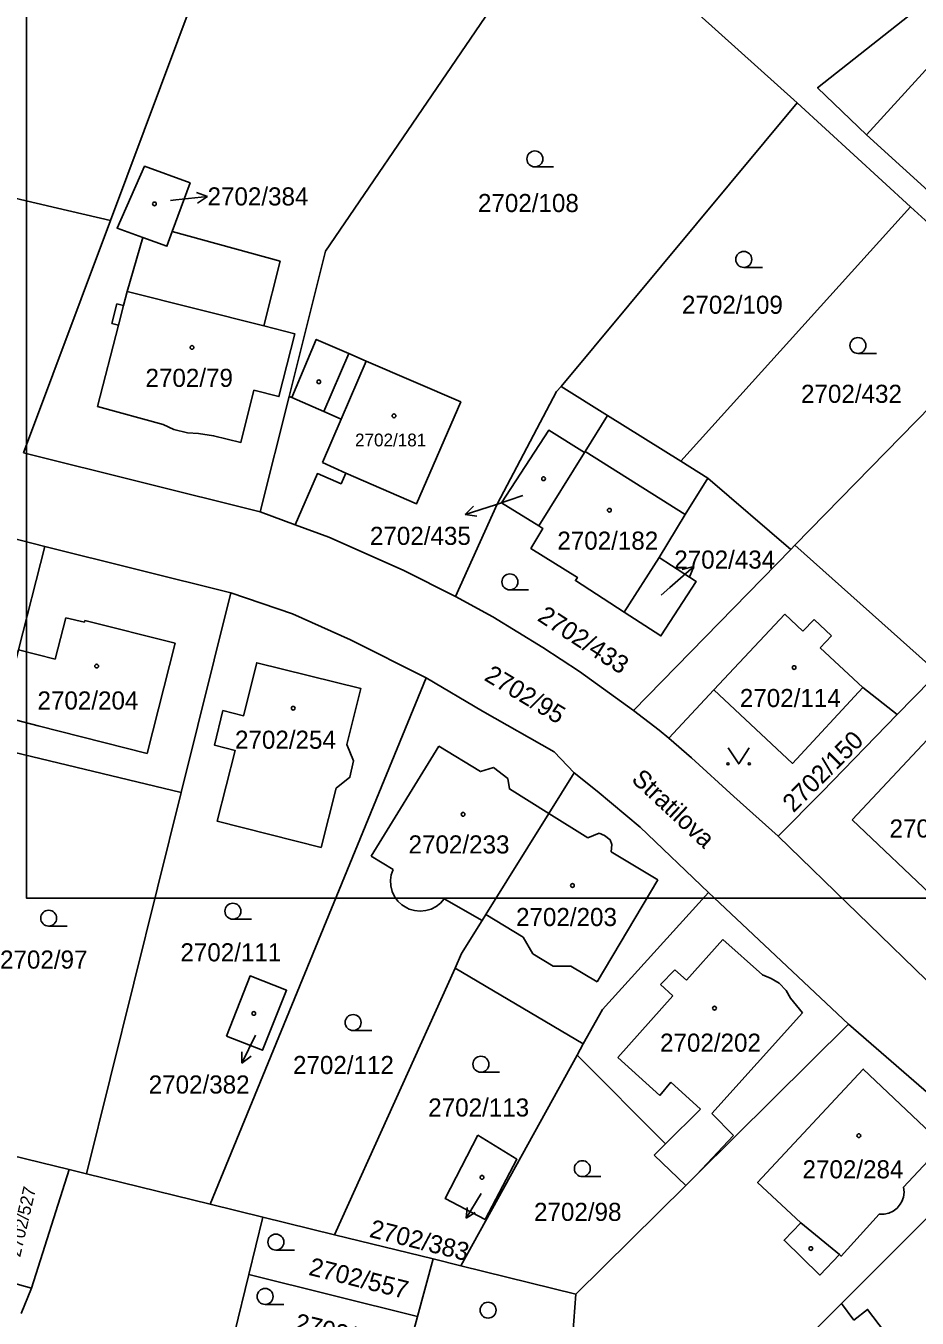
# Model space of a CAD drawing. Extents: x -496682 to -495776, y -1088797 to -1088018.
# Drawn here: x -496557.4 to -496473.7, y -1088500.7 to -1088379.3 of the extents above; entities that cross this region are included whole.
import ezdxf

# ---------------------------------------------------------------- set-up
doc = ezdxf.new("R2010")
doc.units = 0
for name, color, linetype in [('Hranice parcel', 7, 'Continuous'), ('Parcelní čísla', 7, 'Continuous'), ('Pop  PČ popisy', 7, 'Continuous'), ('Vnitřní kresba', 7, 'Continuous'), ('Vrstva 63', 7, 'Continuous'), ('Značky budov', 7, 'Continuous'), ('Značky kultur', 7, 'Continuous')]:
    doc.layers.add(name, color=color, linetype=linetype)

msp = doc.modelspace()

# ---------------------------------------------------------------- linework, layer by layer
at = {"layer": 'Hranice parcel'}
for p, q in [((-496549.47, -1088397.55), (-496534.41, -1088357.28)), ((-496484.94, -1088386.51), (-496506.52, -1088367.06)), ((-496507.11, -1088413.15), (-496484.94, -1088386.51)), ((-496474.27, -1088396.26), (-496484.94, -1088386.51)), ((-496495.87, -1088420.18), (-496474.27, -1088396.26)), ((-496557.63, -1088419.38), (-496549.47, -1088397.55)), ((-496463.6, -1088406), (-496485.14, -1088428.06)), ((-496507.11, -1088413.15), (-496502.75, -1088415.88)), ((-496535.38, -1088424.94), (-496532.68, -1088414.09)), ((-496502.75, -1088415.88), (-496495.87, -1088420.18)), ((-496557.63, -1088419.38), (-496535.38, -1088424.94)), ((-496504.92, -1088419.36), (-496509.22, -1088426.26)), ((-496493.32, -1088421.78), (-496495.87, -1088420.18)), ((-496580.96, -1088421.7), (-496555.62, -1088428.18)), ((-496493.32, -1088421.78), (-496485.53, -1088428.46)), ((-496532.1, -1088426.15), (-496535.38, -1088424.94)), ((-496555.62, -1088428.18), (-496538.16, -1088432.53)), ((-496485.53, -1088428.46), (-496500.3, -1088443.59)), ((-496485.14, -1088428.06), (-496485.53, -1088428.46)), ((-496471.71, -1088440.06), (-496485.14, -1088428.06)), ((-496501.2, -1088434.35), (-496497.9, -1088429.23)), ((-496538.16, -1088432.53), (-496542.82, -1088451.3)), ((-496540.08, -1088490.01), (-496519.8, -1088440.54)), ((-496472.38, -1088440.74), (-496475.55, -1088443.98)), ((-496542.82, -1088451.3), (-496560.5, -1088447.06)), ((-496524.96, -1088457.28), (-496518.62, -1088446.95)), ((-496513.47, -1088448.95), (-496512.11, -1088449.99)), ((-496508.27, -1088453.28), (-496505.89, -1088449.46)), ((-496551.73, -1088487.14), (-496542.82, -1088451.3)), ((-496486.71, -1088455.42), (-496471.75, -1088469.95)), ((-496522.91, -1088458.54), (-496524.96, -1088457.28)), ((-496493.26, -1088460.72), (-496480.12, -1088473.09)), ((-496514.53, -1088463.34), (-496518.09, -1088461.3)), ((-496528.42, -1088492.87), (-496517.08, -1088467.81)), ((-496505.03, -1088474.94), (-496517.08, -1088467.81)), ((-496480.12, -1088473.09), (-496466.41, -1088484.97)), ((-496505.61, -1088476), (-496505.03, -1088474.94)), ((-496516.53, -1088495.79), (-496505.61, -1088476)), ((-496562.76, -1088484.43), (-496553.34, -1088486.74)), ((-496480.76, -1088499.32), (-496466.41, -1088484.97)), ((-496495.38, -1088488.23), (-496498.38, -1088485.38)), ((-496553.34, -1088486.74), (-496556.89, -1088497.88)), ((-496551.73, -1088487.14), (-496553.34, -1088486.74)), ((-496540.08, -1088490.01), (-496551.73, -1088487.14)), ((-496495.38, -1088488.23), (-496505.72, -1088498.45)), ((-496535.15, -1088491.22), (-496540.08, -1088490.01)), ((-496536.46, -1088496.6), (-496535.15, -1088491.22)), ((-496535.15, -1088491.22), (-496528.42, -1088492.87)), ((-496528.42, -1088492.87), (-496519.15, -1088495.15)), ((-496565.8, -1088495.44), (-496556.89, -1088497.88)), ((-496520.6, -1088500.55), (-496519.15, -1088495.15)), ((-496519.15, -1088495.15), (-496516.53, -1088495.79)), ((-496505.72, -1088498.45), (-496516.53, -1088495.79)), ((-496537.8, -1088502.11), (-496536.46, -1088496.6)), ((-496520.6, -1088500.55), (-496536.46, -1088496.6)), ((-496556.89, -1088497.88), (-496557.86, -1088500.28)), ((-496505.72, -1088498.45), (-496506.52, -1088508.66)), ((-496479.61, -1088500.91), (-496480.76, -1088499.32)), ((-496522.01, -1088505.76), (-496520.6, -1088500.55))]:
    msp.add_line(p, q, dxfattribs=at)
for points in [[(-496532.68, -1088414.09), (-496529.27, -1088400.43), (-496506.52, -1088367.06)], [(-496458.81, -1088390.16), (-496459.62, -1088391.05), (-496452.7, -1088397.45), (-496448.2, -1088392.71), (-496455.1, -1088386.16), (-496452.66, -1088383.51), (-496456.87, -1088379.65), (-496455.18, -1088377.81), (-496462.05, -1088371.53), (-496462.96, -1088372.53), (-496463.92, -1088371.65), (-496464.44, -1088372.21), (-496465.37, -1088371.11), (-496483.02, -1088385.08), (-496478.41, -1088389.5), (-496471.58, -1088395.72), (-496463.03, -1088386.33), (-496458.81, -1088390.16)], [(-496574.52, -1088391.68), (-496554.43, -1088396.39), (-496549.47, -1088397.55)], [(-496546.43, -1088399.15), (-496548.84, -1088398.28), (-496546.26, -1088392.45), (-496541.98, -1088394.02), (-496543.65, -1088398.6)], [(-496474.27, -1088396.26), (-496465.34, -1088404.42), (-496463.6, -1088406)], [(-496543.65, -1088398.6), (-496533.53, -1088401.39), (-496535.05, -1088407.46), (-496532.14, -1088408.2), (-496533.63, -1088414.1), (-496535.98, -1088413.51), (-496537.21, -1088418.41), (-496539.77, -1088417.78), (-496541.18, -1088417.56), (-496542.21, -1088417.51), (-496543.51, -1088417.18), (-496544.5, -1088416.71), (-496550.68, -1088415.02), (-496548.71, -1088407.38), (-496549.32, -1088407.23), (-496548.85, -1088405.39), (-496548.24, -1088405.55), (-496547.9, -1088404.23), (-496546.43, -1088399.15)], [(-496543.65, -1088398.6), (-496544.16, -1088399.98), (-496546.43, -1088399.15)], [(-496532.68, -1088414.09), (-496532.43, -1088414.19), (-496530.13, -1088408.73), (-496527.05, -1088410.06), (-496525.42, -1088410.77), (-496516.55, -1088414.6), (-496520.69, -1088424.17), (-496527.35, -1088421.29), (-496527.79, -1088422.29), (-496530.01, -1088421.34), (-496532.1, -1088426.15)], [(-496517.03, -1088432.88), (-496513.11, -1088424.21), (-496507.54, -1088413.62), (-496507.11, -1088413.15)], [(-496502.75, -1088415.88), (-496504.86, -1088419.27), (-496504.92, -1088419.36)], [(-496509.22, -1088426.26), (-496512.71, -1088424.09), (-496508.27, -1088417.26), (-496504.92, -1088419.36)], [(-496497.9, -1088429.23), (-496495.45, -1088425.18), (-496493.32, -1088421.78)], [(-496517.03, -1088432.88), (-496521.97, -1088430.43), (-496528.95, -1088427.3), (-496532.1, -1088426.15)], [(-496509.22, -1088426.26), (-496508.83, -1088426.51), (-496509.96, -1088428.37), (-496505.58, -1088431.1), (-496505.77, -1088431.4), (-496501.2, -1088434.35)], [(-496555.62, -1088428.18), (-496558.12, -1088437.89), (-496559.72, -1088444.15), (-496560.5, -1088447.06)], [(-496497.9, -1088429.23), (-496494.43, -1088431.47), (-496497.73, -1088436.59), (-496501.2, -1088434.35)], [(-496538.16, -1088432.53), (-496532.37, -1088434.53), (-496526.9, -1088436.97), (-496519.8, -1088440.54)], [(-496500.3, -1088443.59), (-496505.39, -1088439.93), (-496508.83, -1088437.68), (-496513.52, -1088434.81), (-496517.03, -1088432.88)], [(-496529.66, -1088456.47), (-496539.44, -1088453.99), (-496537.75, -1088447.35), (-496539.7, -1088446.85), (-496538.9, -1088443.61), (-496536.95, -1088444.09), (-496535.71, -1088439.11), (-496525.94, -1088441.53), (-496527.25, -1088446.79), (-496526.61, -1088448.32), (-496526.96, -1088449.87), (-496528.25, -1088450.89), (-496529.66, -1088456.47)], [(-496519.8, -1088440.54), (-496514.5, -1088443.66), (-496507.77, -1088447.5), (-496505.89, -1088449.46)], [(-496497, -1088446.21), (-496492.75, -1088441.67), (-496485.37, -1088448.58), (-496478.75, -1088441.43), (-496475.55, -1088443.98)], [(-496497, -1088446.21), (-496497.89, -1088445.44), (-496500.3, -1088443.59)], [(-496475.55, -1088443.98), (-496482.58, -1088451.24), (-496486.71, -1088455.42)], [(-496518.62, -1088446.95), (-496514.7, -1088449.35), (-496513.47, -1088448.95)], [(-496486.71, -1088455.42), (-496490.9, -1088451.69), (-496494.87, -1088448.06), (-496497, -1088446.21)], [(-496505.89, -1088449.46), (-496503.74, -1088451.18), (-496499.69, -1088454.56), (-496493.26, -1088460.72)], [(-496512.11, -1088449.99), (-496511.97, -1088450.97), (-496508.27, -1088453.28)], [(-496508.27, -1088453.28), (-496514.18, -1088462.78), (-496514.53, -1088463.34)], [(-496518.09, -1088461.3), (-496518.44, -1088461.7), (-496518.85, -1088462.02), (-496519.33, -1088462.26), (-496519.83, -1088462.41), (-496520.36, -1088462.46), (-496520.89, -1088462.41), (-496521.39, -1088462.26), (-496521.62, -1088462.16), (-496522.07, -1088461.87), (-496522.45, -1088461.51), (-496522.76, -1088461.08), (-496522.99, -1088460.6), (-496523.12, -1088460.09), (-496523.15, -1088459.56), (-496523.08, -1088459.04), (-496522.91, -1088458.54)], [(-496505.03, -1088474.94), (-496503.24, -1088471.69), (-496493.26, -1088460.72)], [(-496517.08, -1088467.81), (-496516.46, -1088466.44), (-496514.53, -1088463.34)], [(-496538.56, -1088474.21), (-496536.35, -1088468.55), (-496532.92, -1088469.9), (-496535.17, -1088475.53), (-496538.56, -1088474.21)], [(-496480.12, -1088473.09), (-496494.39, -1088487.23), (-496495.38, -1088488.23)], [(-496498.38, -1088485.38), (-496497.3, -1088484.32), (-496505.61, -1088476)], [(-496477.23, -1088490.95), (-496480.8, -1088494.89), (-496480.96, -1088494.74), (-496482.79, -1088496.66), (-496486.16, -1088493.39), (-496484.58, -1088491.75), (-496488.65, -1088487.95), (-496478.73, -1088477.31), (-496471.2, -1088484.41), (-496474.93, -1088488.41)], [(-496514.25, -1088491.45), (-496518.01, -1088489.48), (-496514.94, -1088483.51)], [(-496514.94, -1088483.51), (-496511.27, -1088485.78), (-496514.25, -1088491.45)], [(-496474.93, -1088488.41), (-496474.89, -1088488.87), (-496474.94, -1088489.33), (-496475.1, -1088489.76), (-496475.24, -1088490.01), (-496475.54, -1088490.37), (-496475.9, -1088490.65), (-496476.32, -1088490.85), (-496476.77, -1088490.95), (-496477.23, -1088490.95)], [(-496507.29, -1088518.51), (-496500.51, -1088519.07), (-496480.76, -1088499.32)], [(-496476.06, -1088505.83), (-496474.64, -1088504.74), (-496478.32, -1088499.89), (-496479.61, -1088500.91)]]:
    msp.add_lwpolyline(points, dxfattribs=at)
at = {"layer": 'Pop  PČ popisy'}
for p, q in [((-496540.34, -1088395.31), (-496541.38, -1088394.91)), ((-496543.82, -1088395.67), (-496543.32, -1088395.62)), ((-496543.32, -1088395.62), (-496540.34, -1088395.31)), ((-496540.34, -1088395.31), (-496541.28, -1088395.91)), ((-496513.29, -1088424.26), (-496516.14, -1088425.19)), ((-496510.7, -1088423.39), (-496513.29, -1088424.26)), ((-496516.14, -1088425.19), (-496515.35, -1088424.4)), ((-496516.14, -1088425.19), (-496515.04, -1088425.35)), ((-496496.91, -1088432.05), (-496494.65, -1088430.08)), ((-496494.65, -1088430.08), (-496495.73, -1088430.36)), ((-496494.65, -1088430.08), (-496495.07, -1088431.12)), ((-496497.7, -1088432.75), (-496496.91, -1088432.05)), ((-496535.83, -1088474.12), (-496537.12, -1088476.76)), ((-496537.12, -1088476.76), (-496537.13, -1088475.67)), ((-496537.12, -1088476.76), (-496536.25, -1088476.1)), ((-496514.64, -1088489), (-496516.03, -1088491.31)), ((-496516.03, -1088491.31), (-496515.95, -1088490.31)), ((-496516.03, -1088491.31), (-496515.18, -1088490.77))]:
    msp.add_line(p, q, dxfattribs=at)
at = {"layer": 'Vnitřní kresba'}
for p, q in [((-496478.41, -1088389.5), (-496463.48, -1088373.09)), ((-496547.9, -1088404.23), (-496535.05, -1088407.46)), ((-496548.24, -1088405.55), (-496548.71, -1088407.38)), ((-496527.05, -1088410.06), (-496529.41, -1088415.51)), ((-496525.42, -1088410.77), (-496527.78, -1088416.21)), ((-496529.41, -1088415.51), (-496532.43, -1088414.19)), ((-496527.78, -1088416.21), (-496529.41, -1088415.51)), ((-496529.55, -1088420.29), (-496527.78, -1088416.21)), ((-496495.45, -1088425.18), (-496504.86, -1088419.27)), ((-496529.55, -1088420.29), (-496527.35, -1088421.29)), ((-496554.65, -1088438.77), (-496553.66, -1088434.88)), ((-496553.66, -1088434.88), (-496551.91, -1088435.31)), ((-496551.91, -1088435.31), (-496551.88, -1088435.14)), ((-496551.88, -1088435.14), (-496543.37, -1088437.28)), ((-496486.09, -1088434.56), (-496492.75, -1088441.67)), ((-496484.4, -1088436.16), (-496486.09, -1088434.56)), ((-496483.35, -1088435.06), (-496484.4, -1088436.16)), ((-496481.7, -1088436.58), (-496483.35, -1088435.06)), ((-496543.37, -1088437.28), (-496546.02, -1088447.65)), ((-496482.76, -1088437.72), (-496481.7, -1088436.58)), ((-496558.12, -1088437.89), (-496554.65, -1088438.77)), ((-496478.75, -1088441.43), (-496482.76, -1088437.72)), ((-496556.25, -1088445.03), (-496559.72, -1088444.15)), ((-496546.02, -1088447.65), (-496556.25, -1088445.03)), ((-496479.76, -1088453.88), (-496472.22, -1088445.82)), ((-496508.27, -1088453.28), (-496504.61, -1088455.57)), ((-496471.83, -1088461.4), (-496479.76, -1088453.88)), ((-496504.61, -1088455.57), (-496503.55, -1088455.12)), ((-496503.55, -1088455.12), (-496503.03, -1088455.34)), ((-496503.03, -1088455.34), (-496502.51, -1088455.76)), ((-496502.51, -1088455.76), (-496502.36, -1088456.2)), ((-496502.36, -1088456.2), (-496502.4, -1088456.88)), ((-496502.4, -1088456.88), (-496498.03, -1088459.53)), ((-496498.03, -1088459.53), (-496503.74, -1088469.11)), ((-496510.68, -1088464.89), (-496514.18, -1088462.78)), ((-496509.77, -1088466.46), (-496510.68, -1088464.89)), ((-496495.33, -1088468.94), (-496491.92, -1088465.12)), ((-496491.92, -1088465.12), (-496488.18, -1088468.46)), ((-496507.87, -1088467.64), (-496509.77, -1088466.46)), ((-496506.2, -1088467.64), (-496507.87, -1088467.64)), ((-496503.74, -1088469.11), (-496506.2, -1088467.64)), ((-496497.78, -1088469.34), (-496496.42, -1088467.97)), ((-496496.42, -1088467.97), (-496495.33, -1088468.94)), ((-496488.18, -1088468.46), (-496487.38, -1088468.79)), ((-496487.38, -1088468.79), (-496486.63, -1088469.24)), ((-496486.63, -1088469.24), (-496485.98, -1088469.91)), ((-496501.8, -1088476.2), (-496496.63, -1088470.41)), ((-496496.63, -1088470.41), (-496497.78, -1088469.34)), ((-496485.98, -1088469.91), (-496485.56, -1088470.63)), ((-496485.56, -1088470.63), (-496484.43, -1088472.03)), ((-496484.43, -1088472.03), (-496492.96, -1088481.47)), ((-496497.85, -1088479.78), (-496501.8, -1088476.2)), ((-496496.82, -1088478.54), (-496497.85, -1088479.78)), ((-496494.03, -1088481.07), (-496496.82, -1088478.54)), ((-496497.3, -1088484.32), (-496494.03, -1088481.07)), ((-496492.96, -1088481.47), (-496490.92, -1088483.54)), ((-496494.39, -1088487.23), (-496490.92, -1088483.54)), ((-496480.96, -1088494.74), (-496484.58, -1088491.75))]:
    msp.add_line(p, q, dxfattribs=at)
at = {"layer": 'Vrstva 63'}
msp.add_lwpolyline([(-496137.35, -1088164.24), (-496137.35, -1088461.24), (-496557.35, -1088461.24), (-496557.35, -1088164.24)], close=True, dxfattribs=at)
at = {"layer": 'Značky budov'}
for centre in [(-496545.33, -1088395.99), (-496541.8, -1088409.48), (-496529.89, -1088412.71), (-496522.82, -1088415.91), (-496508.76, -1088421.82), (-496502.58, -1088424.78), (-496550.76, -1088439.43), (-496485.22, -1088439.57), (-496532.29, -1088443.39), (-496516.33, -1088453.36), (-496506.05, -1088460.05), (-496492.7, -1088471.58), (-496536, -1088472.07), (-496479.14, -1088483.56), (-496514.55, -1088487.48), (-496483.65, -1088494.17)]:
    msp.add_circle(centre, 0.175, dxfattribs=at)
at = {"layer": 'Značky kultur'}
for p, q in [((-496509.58, -1088392.52), (-496507.83, -1088392.52)), ((-496489.95, -1088401.96), (-496488.2, -1088401.96)), ((-496479.22, -1088410.05), (-496477.47, -1088410.05)), ((-496511.93, -1088432.27), (-496510.18, -1088432.27)), ((-496555.27, -1088463.87), (-496553.52, -1088463.87)), ((-496537.96, -1088463.22), (-496536.21, -1088463.22)), ((-496526.66, -1088473.68), (-496524.91, -1088473.68)), ((-496514.65, -1088477.6), (-496512.9, -1088477.6)), ((-496505.12, -1088487.41), (-496503.37, -1088487.41)), ((-496533.92, -1088494.31), (-496532.17, -1088494.31)), ((-496534.93, -1088499.42), (-496533.18, -1088499.42))]:
    msp.add_line(p, q, dxfattribs=at)
msp.add_lwpolyline([(-496491.43, -1088447.12), (-496490.43, -1088448.62), (-496489.43, -1088447.12)], dxfattribs=at)
for centre, radius in [((-496509.58, -1088391.77), 0.75), ((-496489.95, -1088401.21), 0.75), ((-496479.22, -1088409.3), 0.75), ((-496511.93, -1088431.52), 0.75), ((-496491.43, -1088448.62), 0.1), ((-496489.43, -1088448.62), 0.1), ((-496537.96, -1088462.47), 0.75), ((-496555.27, -1088463.12), 0.75), ((-496526.66, -1088472.93), 0.75), ((-496514.65, -1088476.85), 0.75), ((-496505.12, -1088486.66), 0.75), ((-496533.92, -1088493.56), 0.75), ((-496534.93, -1088498.67), 0.75), ((-496513.98, -1088499.96), 0.75)]:
    msp.add_circle(centre, radius, dxfattribs=at)

# ---------------------------------------------------------------- texts
at = {"layer": 'Parcelní čísla'}
for s, height, p in [('2702/384', 1.7, (-496540.34, -1088396.14)), ('2702/108', 1.7, (-496514.93, -1088396.76)), ('2702/109', 1.7, (-496495.76, -1088406.32)), ('2702/79', 1.7, (-496546.17, -1088413.19)), ('2702/432', 1.7, (-496484.57, -1088414.69)), ('2702/181', 1.2, (-496526.48, -1088418.78)), ('2702/435', 1.7, (-496525.08, -1088428.04)), ('2702/182', 1.7, (-496507.47, -1088428.49)), ('2702/434', 1.7, (-496496.48, -1088430.27)), ('2702/204', 1.7, (-496556.32, -1088443.51)), ('2702/114', 1.7, (-496490.32, -1088443.28)), ('2702/254', 1.7, (-496537.76, -1088447.2)), ('2702/80', 1.7, (-496476.25, -1088455.54)), ('2702/233', 1.7, (-496521.45, -1088457.04)), ('2702/203', 1.7, (-496511.35, -1088463.86)), ('2702/111', 1.7, (-496542.89, -1088467.18)), ('2702/97', 1.7, (-496559.84, -1088467.86)), ('2702/202', 1.7, (-496497.82, -1088475.67)), ('2702/112', 1.7, (-496532.31, -1088477.77)), ('2702/382', 1.7, (-496545.87, -1088479.6)), ('2702/113', 1.7, (-496519.6, -1088481.76)), ('2702/284', 1.7, (-496484.43, -1088487.57)), ('2702/98', 1.7, (-496509.66, -1088491.57))]:
    msp.add_text(s, height=height, dxfattribs=at).set_placement(p)
for s, height, rotation, p in [('2702/433', 1.7, 327, (-496509.44, -1088435.09)), ('2702/95', 1.7, 329, (-496514.44, -1088440.7)), ('2702/150', 1.7, 45, (-496485.28, -1088453.27)), ('2702/527', 1.2, 77, (-496557.95, -1088495.03)), ('2702/383', 1.7, 346, (-496525.22, -1088493.06)), ('2702/557', 1.7, 346, (-496530.92, -1088496.63)), ('2702/556', 1.7, 346, (-496532.26, -1088501.87))]:
    msp.add_text(s, height=height, rotation=rotation, dxfattribs=at).set_placement(p)
at = {"layer": 'Pop  PČ popisy'}
msp.add_text('Stratilova', height=1.7, rotation=317, dxfattribs=at).set_placement((-496500.6, -1088450.19))

doc.saveas('drawing.dxf')
